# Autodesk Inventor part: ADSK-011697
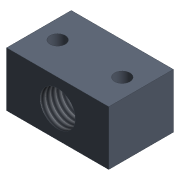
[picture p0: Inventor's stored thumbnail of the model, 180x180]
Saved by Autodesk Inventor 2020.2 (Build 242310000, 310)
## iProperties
Created: 2000-03
Part Number: ADSK-011697
Material: Pearson Nylatron
Description: PLT-03,SN,EX,023,012,999,ACME_LIFT_NUT,LH
Document SubType Name: Modeling
Designer: sspink
Density: 1.13867 g/cm^3
Appearance: Nylatron
Mass: 61.4883 g
Surface Area: 145.273 cm^2
Volume: 54.0001 cm^3
Control State: 0
Master: False
Checked Out: False
Shininess: 10.0
Length Units: 11269
Angle Units: 11279
Time Units: 11290
Mass Units: 11283
Length Display Precision: 3
Angle Display Precision: 2
Compacted: True
Cutlength: 2.38 X 1.25 (3.00 SI)
Material Desc: SHEET,NYLATRON,1.500
Material_Number: A102223
Dimensions: 32x38x60 mm
Mass: 0,061 kg
VLT_Material: Pearson Nylatron
Density: 1.13867
Volumn: 72.97364437499999
Area: 108.467525
PropertySet Name: Model Information
Author: sspink
Revision Number: -
Title: PLT-03,SN,EX,023,012,999,ACME_LIFT_NUT,LH
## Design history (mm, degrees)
sketch "Sketch3"
  geometry: L1 (11, 19)-(49, 19); L2 (0, 0)-(60, 0) reference; L3 (0, 38)-(0, 0) reference; 3 further points
  constraints: 3 midpoint, 2 end point, 1 horizontal, 1 horizontal alignment, 1 vertical alignment
  dimensions: "d24" = 38 distance of L1.start L1.end
node "Hole2" dims "d12" = 9, "d13" = 15, "d14" = 9, "d15" = 60 deg, "d16" = 19.05, "d17" = 118 deg, "d23" = 6
node "Solide1"
  node "Extrusion1" dims "d2" = 38, "d3" = 0
  node "Hole1" dims "d4" = 20.752, "d5" = 9.525, "d6" = 6.35, "d7" = 60 deg, "d8" = 61.1, "d9" = 118 deg, "d22" = 48
sketch "Sketch1"
  geometry: L1 (0, 0)-(60, 0); L2 (60, 0)-(60, 32); L3 (60, 32)-(0, 32); L4 (0, 32)-(0, 0)
  constraints: 8 end point, 2 parallel, 1 horizontal, 1 perpendicular
  dimensions: "d0" = 32 distance between parallel lines of L3 L1; "d1" = 60 distance between parallel lines of L2 L4
sketch "Sketch2"
  geometry: L1 (0, 0)-(0, 32) reference; L2 (60, 0)-(0, 0) reference; L3 (60, 32)-(60, 0) reference; L4 (0, 32)-(60, 32) reference; L5 (0, 16)-(60, 16); L6 (30, 32)-(30, 0); 1 further point
  constraints: 5 midpoint, 4 end point
node "Corps solides"
node "Corps surfaciques"
